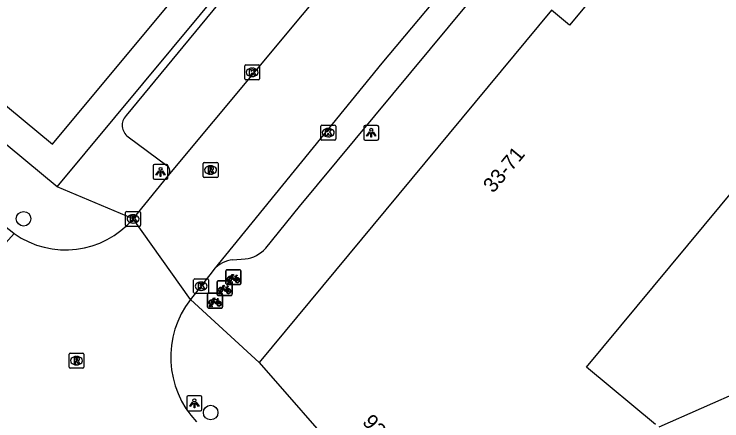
# Model space of a CAD drawing. Extents: x 162074 to 163034, y 381824 to 382557.
# Drawn here: x 162266.75 to 162314.17, y 382043.06 to 382070.34 of the extents above; entities that cross this region are included whole.
import ezdxf

# ---------------------------------------------------------------- set-up
doc = ezdxf.new("R2010")
doc.units = 0
for name, color, linetype in [('IMGEO_Boom', 7, 'Continuous'), ('IMGEO_Fietsenrek', 7, 'Continuous'), ('IMGEO_Kolk', 7, 'Continuous'), ('IMGEO_Lichtpunt', 7, 'Continuous'), ('IMGEO_Pand', 7, 'Continuous'), ('IMGEO_Pand_nummerreeks', 7, 'Continuous'), ('IMGEO_Rijbaan_lokaal_open', 7, 'Continuous'), ('IMGEO_Rioolput', 7, 'Continuous'), ('IMGEO_Voetpad_open', 7, 'Continuous')]:
    doc.layers.add(name, color=color, linetype=linetype)

msp = doc.modelspace()

# ---------------------------------------------------------------- linework, layer by layer
at = {"layer": 'IMGEO_Boom'}
for centre in [(162267.372, 382056.618), (162279.913, 382043.619)]:
    msp.add_circle(centre, 0.489, dxfattribs=at)
at = {"layer": 'IMGEO_Fietsenrek'}
for p, q in [((162280.94, 382052.275), (162280.94, 382053.116)), ((162280.94, 382053.116), (162280.94, 382052.275)), ((162281.015, 382053.2), (162281.856, 382053.2)), ((162281.856, 382053.2), (162281.015, 382053.2)), ((162281.94, 382053.125), (162281.94, 382052.284)), ((162281.94, 382052.284), (162281.94, 382053.125)), ((162281.627, 382052.749), (162281.663, 382052.654)), ((162280.344, 382051.54), (162280.344, 382052.381)), ((162280.344, 382052.381), (162280.344, 382051.54)), ((162280.419, 382052.465), (162281.26, 382052.465)), ((162281.26, 382052.465), (162280.419, 382052.465)), ((162281.865, 382052.2), (162281.024, 382052.2)), ((162281.024, 382052.2), (162281.865, 382052.2)), ((162281.067, 382052.284), (162281.106, 382052.444)), ((162281.101, 382052.284), (162281.067, 382052.284)), ((162281.136, 382052.432), (162281.101, 382052.284)), ((162281.178, 382052.456), (162281.177, 382052.46)), ((162281.219, 382052.284), (162281.185, 382052.426)), ((162281.209, 382052.467), (162281.21, 382052.46)), ((162281.217, 382052.43), (162281.252, 382052.284)), ((162281.252, 382052.284), (162281.219, 382052.284)), ((162281.344, 382052.39), (162281.344, 382051.549)), ((162281.344, 382051.549), (162281.344, 382052.39)), ((162279.783, 382051.622), (162280.624, 382051.622)), ((162280.624, 382051.622), (162279.783, 382051.622)), ((162280.471, 382051.549), (162280.51, 382051.709)), ((162280.54, 382051.697), (162280.505, 382051.549)), ((162280.582, 382051.721), (162280.581, 382051.725)), ((162280.623, 382051.549), (162280.589, 382051.691)), ((162280.613, 382051.732), (162280.614, 382051.725)), ((162280.621, 382051.695), (162280.656, 382051.549)), ((162281.031, 382052.014), (162281.067, 382051.919)), ((162279.708, 382050.697), (162279.708, 382051.538)), ((162279.708, 382051.538), (162279.708, 382050.697)), ((162280.395, 382051.171), (162280.431, 382051.076)), ((162281.269, 382051.465), (162280.428, 382051.465)), ((162280.428, 382051.465), (162281.269, 382051.465)), ((162280.505, 382051.549), (162280.471, 382051.549)), ((162280.656, 382051.549), (162280.623, 382051.549)), ((162280.708, 382051.547), (162280.708, 382050.706)), ((162280.708, 382050.706), (162280.708, 382051.547)), ((162280.633, 382050.622), (162279.792, 382050.622)), ((162279.792, 382050.622), (162280.633, 382050.622)), ((162279.835, 382050.706), (162279.874, 382050.866)), ((162279.869, 382050.706), (162279.835, 382050.706)), ((162279.904, 382050.854), (162279.869, 382050.706)), ((162279.946, 382050.878), (162279.945, 382050.882)), ((162279.987, 382050.706), (162279.953, 382050.848)), ((162279.977, 382050.889), (162279.978, 382050.882)), ((162279.985, 382050.852), (162280.02, 382050.706)), ((162280.02, 382050.706), (162279.987, 382050.706))]:
    msp.add_line(p, q, dxfattribs=at)
for points in [[(162281.274, 382052.674), (162281.222, 382052.584), (162281.182, 382052.559), (162281.183, 382052.606), (162281.238, 382052.7)], [(162281.253, 382052.726), (162281.348, 382052.89), (162281.434, 382052.876), (162281.436, 382052.867), (162281.38, 382052.856), (162281.353, 382052.811), (162281.609, 382052.77)], [(162281.549, 382052.482), (162281.499, 382052.482), (162281.308, 382052.733), (162281.289, 382052.701)], [(162281.596, 382052.745), (162281.339, 382052.786), (162281.322, 382052.757), (162281.489, 382052.537), (162281.596, 382052.745)], [(162281.644, 382052.647), (162281.614, 382052.724), (162281.505, 382052.506), (162281.548, 382052.506)], [(162281.578, 382052.506), (162281.698, 382052.505), (162281.654, 382052.619)], [(162281.674, 382052.626), (162281.729, 382052.481), (162281.579, 382052.481)], [(162281.609, 382052.77), (162281.634, 382052.819), (162281.628, 382052.823), (162281.605, 382052.827), (162281.593, 382052.834), (162281.592, 382052.837), (162281.594, 382052.842), (162281.689, 382052.827), (162281.691, 382052.817), (162281.681, 382052.804), (162281.669, 382052.798), (162281.655, 382052.804), (162281.627, 382052.749)], [(162280.657, 382051.991), (162280.752, 382052.155), (162280.838, 382052.141), (162280.84, 382052.132), (162280.784, 382052.121), (162280.757, 382052.076), (162281.013, 382052.035)], [(162281, 382052.01), (162280.743, 382052.051), (162280.726, 382052.022), (162280.893, 382051.802), (162281, 382052.01)], [(162281.013, 382052.035), (162281.038, 382052.084), (162281.032, 382052.088), (162281.009, 382052.092), (162280.997, 382052.099), (162280.996, 382052.102), (162280.998, 382052.107), (162281.093, 382052.092), (162281.095, 382052.082), (162281.085, 382052.069), (162281.073, 382052.063), (162281.059, 382052.069), (162281.031, 382052.014)], [(162280.678, 382051.939), (162280.626, 382051.849), (162280.586, 382051.824), (162280.587, 382051.871), (162280.642, 382051.965)], [(162280.953, 382051.747), (162280.903, 382051.747), (162280.712, 382051.998), (162280.693, 382051.966)], [(162281.048, 382051.912), (162281.018, 382051.989), (162280.909, 382051.771), (162280.952, 382051.771)], [(162280.982, 382051.771), (162281.102, 382051.77), (162281.058, 382051.884)], [(162281.078, 382051.891), (162281.133, 382051.746), (162280.983, 382051.746)], [(162280.042, 382051.096), (162279.99, 382051.006), (162279.95, 382050.981), (162279.951, 382051.028), (162280.006, 382051.122)], [(162280.021, 382051.148), (162280.116, 382051.312), (162280.202, 382051.298), (162280.204, 382051.289), (162280.148, 382051.278), (162280.121, 382051.233), (162280.377, 382051.192)], [(162280.317, 382050.904), (162280.267, 382050.904), (162280.076, 382051.155), (162280.057, 382051.123)], [(162280.364, 382051.167), (162280.107, 382051.208), (162280.09, 382051.179), (162280.257, 382050.959), (162280.364, 382051.167)], [(162280.412, 382051.069), (162280.382, 382051.146), (162280.273, 382050.928), (162280.316, 382050.928)], [(162280.377, 382051.192), (162280.402, 382051.241), (162280.396, 382051.245), (162280.373, 382051.249), (162280.361, 382051.256), (162280.36, 382051.259), (162280.362, 382051.264), (162280.457, 382051.249), (162280.459, 382051.239), (162280.449, 382051.226), (162280.437, 382051.22), (162280.423, 382051.226), (162280.395, 382051.171)], [(162280.346, 382050.928), (162280.466, 382050.927), (162280.422, 382051.041)], [(162280.442, 382051.048), (162280.497, 382050.903), (162280.347, 382050.903)]]:
    msp.add_lwpolyline(points, dxfattribs=at)
for centre, radius, start, end in [((162281.018, 382053.122), 0.0779, 92.4484, 184.2845), ((162281.018, 382053.122), 0.0779, 92.4484, 184.2845), ((162281.862, 382053.122), 0.0779, 2.4484, 94.2845), ((162281.862, 382053.122), 0.0779, 2.4484, 94.2845), ((162281.18, 382052.585), 0.159, 62.6766, 242.1369), ((162281.18, 382052.585), 0.129, 63.3192, 238.903), ((162281.18, 382052.585), 0.129, 283.6043, 43.4302), ((162281.18, 382052.585), 0.159, 283.5766, 46.6042), ((162281.707, 382052.501), 0.159, 113.3408, 178.3217), ((162281.707, 382052.501), 0.159, 187.0065, 105.7708), ((162281.707, 382052.501), 0.129, 113.923, 177.9556), ((162281.707, 382052.501), 0.129, 188.6715, 104.5883), ((162280.422, 382052.387), 0.0779, 92.4484, 184.2845), ((162280.422, 382052.387), 0.0779, 92.4484, 184.2845), ((162281.018, 382052.278), 0.0779, 182.4484, 274.2845), ((162281.018, 382052.278), 0.0779, 182.4484, 274.2845), ((162281.16, 382052.456), 0.0499, 12.8025, 158.6934), ((162281.18, 382052.585), 0.159, 253.9967, 271.7867), ((162281.16, 382052.456), 0.0174, 12.8025, 163.4502), ((162281.18, 382052.585), 0.129, 253.415, 269.0204), ((162281.266, 382052.387), 0.0779, 2.4484, 94.2845), ((162281.266, 382052.387), 0.0779, 2.4484, 94.2845), ((162281.862, 382052.278), 0.0779, 272.4484, 4.2845), ((162281.862, 382052.278), 0.0779, 272.4484, 4.2845), ((162279.786, 382051.544), 0.0779, 92.4484, 184.2845), ((162279.786, 382051.544), 0.0779, 92.4484, 184.2845), ((162280.584, 382051.85), 0.159, 62.6766, 242.1369), ((162280.584, 382051.85), 0.129, 63.3192, 238.903), ((162280.564, 382051.721), 0.0499, 12.8025, 158.6934), ((162280.584, 382051.85), 0.159, 253.9967, 271.7867), ((162280.564, 382051.721), 0.0174, 12.8025, 163.4502), ((162280.584, 382051.85), 0.129, 253.415, 269.0204), ((162280.584, 382051.85), 0.129, 283.6043, 43.4302), ((162280.584, 382051.85), 0.159, 283.5766, 46.6042), ((162280.63, 382051.544), 0.0779, 2.4484, 94.2845), ((162280.63, 382051.544), 0.0779, 2.4484, 94.2845), ((162281.111, 382051.766), 0.159, 113.3408, 178.3217), ((162281.111, 382051.766), 0.159, 187.0065, 105.7708), ((162281.111, 382051.766), 0.129, 113.923, 177.9556), ((162281.111, 382051.766), 0.129, 188.6715, 104.5883), ((162279.948, 382051.007), 0.159, 62.6766, 242.1369), ((162279.948, 382051.007), 0.129, 63.3192, 238.903), ((162279.948, 382051.007), 0.129, 283.6043, 43.4302), ((162279.948, 382051.007), 0.159, 283.5766, 46.6042), ((162280.422, 382051.543), 0.0779, 182.4484, 274.2845), ((162280.422, 382051.543), 0.0779, 182.4484, 274.2845), ((162281.266, 382051.543), 0.0779, 272.4484, 4.2845), ((162281.266, 382051.543), 0.0779, 272.4484, 4.2845), ((162279.786, 382050.7), 0.0779, 182.4484, 274.2845), ((162279.786, 382050.7), 0.0779, 182.4484, 274.2845), ((162279.928, 382050.878), 0.0499, 12.8025, 158.6934), ((162279.948, 382051.007), 0.159, 253.9967, 271.7867), ((162279.928, 382050.878), 0.0174, 12.8025, 163.4502), ((162279.948, 382051.007), 0.129, 253.415, 269.0204), ((162280.475, 382050.923), 0.159, 113.3408, 178.3217), ((162280.475, 382050.923), 0.159, 187.0065, 105.7708), ((162280.475, 382050.923), 0.129, 113.923, 177.9556), ((162280.475, 382050.923), 0.129, 188.6715, 104.5883), ((162280.63, 382050.7), 0.0779, 272.4484, 4.2845), ((162280.63, 382050.7), 0.0779, 272.4484, 4.2845)]:
    msp.add_arc(centre, radius, start, end, dxfattribs=at)
at = {"layer": 'IMGEO_Kolk'}
for p, q in [((162282.194, 382066.012), (162282.194, 382066.864)), ((162282.269, 382066.938), (162283.121, 382066.938)), ((162283.195, 382066.864), (162283.195, 382066.012)), ((162282.682, 382066.718), (162282.707, 382066.718)), ((162283.121, 382065.938), (162282.269, 382065.938)), ((162282.705, 382066.158), (162282.68, 382066.158)), ((162287.289, 382061.968), (162287.289, 382062.82)), ((162287.364, 382062.894), (162288.216, 382062.894)), ((162287.777, 382062.674), (162287.802, 382062.674)), ((162288.29, 382062.82), (162288.29, 382061.968)), ((162287.8, 382062.114), (162287.775, 382062.114)), ((162288.216, 382061.894), (162287.364, 382061.894)), ((162274.214, 382056.18), (162274.214, 382057.032)), ((162274.289, 382057.106), (162275.141, 382057.106)), ((162274.702, 382056.886), (162274.727, 382056.886)), ((162275.215, 382057.032), (162275.215, 382056.18)), ((162274.725, 382056.326), (162274.7, 382056.326)), ((162275.141, 382056.106), (162274.289, 382056.106)), ((162278.774, 382051.67), (162278.774, 382052.522)), ((162278.849, 382052.596), (162279.701, 382052.596)), ((162279.775, 382052.522), (162279.775, 382051.67)), ((162279.262, 382052.376), (162279.287, 382052.376)), ((162279.701, 382051.596), (162278.849, 382051.596)), ((162279.285, 382051.816), (162279.26, 382051.816))]:
    msp.add_line(p, q, dxfattribs=at)
for points in [[(162282.194, 382066.012), (162282.194, 382066.864)], [(162282.269, 382066.938), (162283.121, 382066.938)], [(162283.195, 382066.864), (162283.195, 382066.012)], [(162282.515, 382066.638), (162282.638, 382066.638), (162282.638, 382066.487), (162282.768, 382066.638), (162282.932, 382066.638), (162282.786, 382066.487), (162282.939, 382066.238), (162282.787, 382066.238), (162282.702, 382066.402), (162282.638, 382066.335), (162282.638, 382066.238), (162282.515, 382066.238), (162282.515, 382066.638)], [(162283.121, 382065.938), (162282.269, 382065.938)], [(162287.289, 382061.968), (162287.289, 382062.82)], [(162287.364, 382062.894), (162288.216, 382062.894)], [(162287.61, 382062.594), (162287.733, 382062.594), (162287.733, 382062.443), (162287.863, 382062.594), (162288.027, 382062.594), (162287.881, 382062.443), (162288.034, 382062.194), (162287.882, 382062.194), (162287.797, 382062.358), (162287.733, 382062.291), (162287.733, 382062.194), (162287.61, 382062.194), (162287.61, 382062.594)], [(162288.29, 382062.82), (162288.29, 382061.968)], [(162288.216, 382061.894), (162287.364, 382061.894)], [(162274.214, 382056.18), (162274.214, 382057.032)], [(162274.289, 382057.106), (162275.141, 382057.106)], [(162274.535, 382056.806), (162274.658, 382056.806), (162274.658, 382056.655), (162274.788, 382056.806), (162274.952, 382056.806), (162274.806, 382056.655), (162274.959, 382056.406), (162274.807, 382056.406), (162274.722, 382056.57), (162274.658, 382056.503), (162274.658, 382056.406), (162274.535, 382056.406), (162274.535, 382056.806)], [(162275.215, 382057.032), (162275.215, 382056.18)], [(162275.141, 382056.106), (162274.289, 382056.106)], [(162278.774, 382051.67), (162278.774, 382052.522)], [(162278.849, 382052.596), (162279.701, 382052.596)], [(162279.775, 382052.522), (162279.775, 382051.67)], [(162279.095, 382052.296), (162279.218, 382052.296), (162279.218, 382052.145), (162279.348, 382052.296), (162279.512, 382052.296), (162279.366, 382052.145), (162279.519, 382051.896), (162279.367, 382051.896), (162279.282, 382052.06), (162279.218, 382051.993), (162279.218, 382051.896), (162279.095, 382051.896), (162279.095, 382052.296)], [(162279.701, 382051.596), (162278.849, 382051.596)]]:
    msp.add_lwpolyline(points, dxfattribs=at)
for centre, start, end in [((162282.271, 382066.862), 91.552, 178.448), ((162282.271, 382066.862), 91.552, 178.448), ((162283.119, 382066.862), 1.552, 88.448), ((162283.119, 382066.862), 1.552, 88.448), ((162282.271, 382066.014), 181.552, 268.448), ((162282.271, 382066.014), 181.552, 268.448), ((162283.119, 382066.014), 271.552, 358.448), ((162283.119, 382066.014), 271.552, 358.448), ((162287.366, 382062.818), 91.552, 178.448), ((162287.366, 382062.818), 91.552, 178.448), ((162288.214, 382062.818), 1.552, 88.448), ((162288.214, 382062.818), 1.552, 88.448), ((162287.366, 382061.97), 181.552, 268.448), ((162287.366, 382061.97), 181.552, 268.448), ((162288.214, 382061.97), 271.552, 358.448), ((162288.214, 382061.97), 271.552, 358.448), ((162274.291, 382057.03), 91.552, 178.448), ((162274.291, 382057.03), 91.552, 178.448), ((162275.139, 382057.03), 1.552, 88.448), ((162275.139, 382057.03), 1.552, 88.448), ((162274.291, 382056.182), 181.552, 268.448), ((162274.291, 382056.182), 181.552, 268.448), ((162275.139, 382056.182), 271.552, 358.448), ((162275.139, 382056.182), 271.552, 358.448), ((162278.851, 382052.52), 91.552, 178.448), ((162278.851, 382052.52), 91.552, 178.448), ((162279.699, 382052.52), 1.552, 88.448), ((162279.699, 382052.52), 1.552, 88.448), ((162278.851, 382051.672), 181.552, 268.448), ((162278.851, 382051.672), 181.552, 268.448), ((162279.699, 382051.672), 271.552, 358.448), ((162279.699, 382051.672), 271.552, 358.448)]:
    msp.add_arc(centre, 0.0765, start, end, dxfattribs=at)
for centre, major_axis, ratio, start_param, end_param in [((162282.681, 382066.438), (-0.387, 0.002), 0.722429, 4.712389, 7.853982), ((162282.706, 382066.438), (-0.39, 0.002), 0.717154, 1.570796, 4.712389), ((162287.776, 382062.394), (-0.387, 0.002), 0.722429, 4.712389, 7.853982), ((162287.801, 382062.394), (-0.39, 0.002), 0.717154, 1.570796, 4.712389), ((162274.701, 382056.606), (-0.387, 0.002), 0.722429, 4.712389, 7.853982), ((162274.726, 382056.606), (-0.39, 0.002), 0.717154, 1.570796, 4.712389), ((162279.261, 382052.096), (-0.387, 0.002), 0.722429, 4.712389, 7.853982), ((162279.286, 382052.096), (-0.39, 0.002), 0.717154, 1.570796, 4.712389)]:
    msp.add_ellipse(centre, major_axis=major_axis, ratio=ratio, start_param=start_param, end_param=end_param, dxfattribs=at)
at = {"layer": 'IMGEO_Lichtpunt'}
for p, q in [((162290.177, 382062.788), (162290.177, 382061.981)), ((162290.177, 382062.788), (162290.177, 382061.981)), ((162291.079, 382062.883), (162290.271, 382062.883)), ((162291.079, 382062.883), (162290.271, 382062.883)), ((162291.173, 382061.981), (162291.173, 382062.788)), ((162291.173, 382061.981), (162291.173, 382062.788)), ((162290.271, 382061.887), (162291.079, 382061.887)), ((162290.271, 382061.887), (162291.079, 382061.887)), ((162276.056, 382060.164), (162276.056, 382059.357)), ((162276.056, 382060.164), (162276.056, 382059.357)), ((162276.958, 382060.259), (162276.15, 382060.259)), ((162276.958, 382060.259), (162276.15, 382060.259)), ((162277.052, 382059.357), (162277.052, 382060.164)), ((162277.052, 382059.357), (162277.052, 382060.164)), ((162276.15, 382059.263), (162276.958, 382059.263)), ((162276.15, 382059.263), (162276.958, 382059.263)), ((162278.321, 382044.642), (162278.321, 382043.835)), ((162278.321, 382044.642), (162278.321, 382043.835)), ((162279.223, 382044.737), (162278.415, 382044.737)), ((162279.223, 382044.737), (162278.415, 382044.737)), ((162279.317, 382043.835), (162279.317, 382044.642)), ((162279.317, 382043.835), (162279.317, 382044.642)), ((162278.415, 382043.741), (162279.223, 382043.741)), ((162278.415, 382043.741), (162279.223, 382043.741))]:
    msp.add_line(p, q, dxfattribs=at)
for points in [[(162290.551, 382062.452), (162290.59, 382062.424), (162290.402, 382062.162), (162290.364, 382062.189), (162290.551, 382062.452)], [(162290.653, 382062.404), (162290.7, 382062.404), (162290.7, 382062.082), (162290.653, 382062.082), (162290.653, 382062.404)], [(162290.763, 382062.424), (162290.801, 382062.451), (162290.988, 382062.189), (162290.949, 382062.161), (162290.763, 382062.424)], [(162276.43, 382059.828), (162276.469, 382059.8), (162276.281, 382059.538), (162276.243, 382059.565), (162276.43, 382059.828)], [(162276.532, 382059.78), (162276.579, 382059.78), (162276.579, 382059.458), (162276.532, 382059.458), (162276.532, 382059.78)], [(162276.642, 382059.8), (162276.68, 382059.827), (162276.867, 382059.565), (162276.828, 382059.537), (162276.642, 382059.8)], [(162278.695, 382044.306), (162278.734, 382044.278), (162278.546, 382044.016), (162278.508, 382044.043), (162278.695, 382044.306)], [(162278.797, 382044.258), (162278.844, 382044.258), (162278.844, 382043.936), (162278.797, 382043.936), (162278.797, 382044.258)], [(162278.907, 382044.278), (162278.945, 382044.305), (162279.132, 382044.043), (162279.093, 382044.015), (162278.907, 382044.278)]]:
    msp.add_lwpolyline(points, dxfattribs=at)
for centre in [(162290.676, 382062.586), (162276.555, 382059.962), (162278.82, 382044.44)]:
    msp.add_circle(centre, 0.0994, dxfattribs=at)
for centre, start, end in [((162290.271, 382062.788), 90, 180), ((162290.271, 382062.788), 90, 180), ((162291.079, 382062.788), 0, 90), ((162291.079, 382062.788), 0, 90), ((162290.271, 382061.981), 180, 270), ((162290.271, 382061.981), 180, 270), ((162291.079, 382061.981), 270, 0), ((162291.079, 382061.981), 270, 360), ((162276.15, 382060.164), 90, 180), ((162276.15, 382060.164), 90, 180), ((162276.958, 382060.164), 0, 90), ((162276.958, 382060.164), 0, 90), ((162276.15, 382059.357), 180, 270), ((162276.15, 382059.357), 180, 270), ((162276.958, 382059.357), 270, 0), ((162276.958, 382059.357), 270, 360), ((162278.415, 382044.642), 90, 180), ((162278.415, 382044.642), 90, 180), ((162279.223, 382044.642), 0, 90), ((162279.223, 382044.642), 0, 90), ((162278.415, 382043.835), 180, 270), ((162278.415, 382043.835), 180, 270), ((162279.223, 382043.835), 270, 0), ((162279.223, 382043.835), 270, 360)]:
    msp.add_arc(centre, 0.0946, start, end, dxfattribs=at)
at = {"layer": 'IMGEO_Pand'}
for points in [[(162257.354, 382071.559), (162269.325, 382061.62), (162287.263, 382083.228)], [(162311.856, 382079.111), (162303.966, 382069.599), (162302.753, 382070.605), (162283.157, 382046.98)], [(162309.723, 382042.825), (162305.101, 382046.658), (162320.873, 382065.674), (162324.065, 382069.522)], [(162283.157, 382046.98), (162294.651, 382033.839)], [(162318.916, 382041.378), (162315.622, 382045.145), (162309.954, 382042.634)]]:
    msp.add_lwpolyline(points, dxfattribs=at)
at = {"layer": 'IMGEO_Rijbaan_lokaal_open'}
for points in [[(162266.745, 382055.63), (162265.389, 382054.128), (162243.321, 382074.12), (162210.014, 382101.13)], [(162302.72, 382080.595), (162291.389, 382067.054), (162280.133, 382053.209)], [(162277.076, 382059.503), (162292.02, 382077.479)], [(162274.715, 382056.606), (162277.076, 382059.503)], [(162278.563, 382051.21), (162274.715, 382056.606)], [(162280.133, 382053.209), (162280.019, 382053.069), (162278.563, 382051.21)]]:
    msp.add_lwpolyline(points, dxfattribs=at)
for centre, radius, start, end in [((162270.195, 382060.485), 5.956, 234.5992, 319.364), ((162283.576, 382047.335), 6.336, 142.2932, 223.2264)]:
    msp.add_arc(centre, radius, start, end, dxfattribs=at)
at = {"layer": 'IMGEO_Rioolput'}
for p, q in [((162279.404, 382059.462), (162279.404, 382060.314)), ((162279.479, 382060.388), (162280.331, 382060.388)), ((162279.892, 382060.168), (162279.917, 382060.168)), ((162280.405, 382060.314), (162280.405, 382059.462)), ((162280.331, 382059.388), (162279.479, 382059.388)), ((162279.915, 382059.608), (162279.89, 382059.608)), ((162270.423, 382046.674), (162270.423, 382047.526)), ((162270.498, 382047.6), (162271.35, 382047.6)), ((162270.911, 382047.38), (162270.936, 382047.38)), ((162271.424, 382047.526), (162271.424, 382046.674)), ((162271.35, 382046.6), (162270.498, 382046.6)), ((162270.934, 382046.82), (162270.909, 382046.82))]:
    msp.add_line(p, q, dxfattribs=at)
for points in [[(162279.404, 382059.462), (162279.404, 382060.314)], [(162279.479, 382060.388), (162280.331, 382060.388)], [(162280.405, 382060.314), (162280.405, 382059.462)], [(162279.993, 382060.086), (162279.741, 382060.088), (162279.741, 382059.688)], [(162279.741, 382059.688), (162279.865, 382059.688), (162279.865, 382059.85), (162279.876, 382059.85)], [(162279.919, 382060.007), (162279.865, 382060.007), (162279.865, 382059.926)], [(162279.865, 382059.926), (162279.917, 382059.926)], [(162279.923, 382059.821), (162279.994, 382059.688), (162280.134, 382059.688), (162280.069, 382059.814)], [(162280.331, 382059.388), (162279.479, 382059.388)], [(162270.423, 382046.674), (162270.423, 382047.526)], [(162270.498, 382047.6), (162271.35, 382047.6)], [(162271.424, 382047.526), (162271.424, 382046.674)], [(162271.012, 382047.298), (162270.76, 382047.3), (162270.76, 382046.9)], [(162270.76, 382046.9), (162270.884, 382046.9), (162270.884, 382047.062), (162270.895, 382047.062)], [(162270.938, 382047.219), (162270.884, 382047.219), (162270.884, 382047.138)], [(162270.884, 382047.138), (162270.936, 382047.138)], [(162270.942, 382047.033), (162271.013, 382046.9), (162271.153, 382046.9), (162271.088, 382047.026)], [(162271.35, 382046.6), (162270.498, 382046.6)]]:
    msp.add_lwpolyline(points, dxfattribs=at)
for centre, radius, start, end in [((162279.481, 382060.312), 0.0765, 91.552, 178.448), ((162279.481, 382060.312), 0.0765, 91.552, 178.448), ((162280.329, 382060.312), 0.0765, 1.552, 88.448), ((162280.329, 382060.312), 0.0765, 1.552, 88.448), ((162279.875, 382059.797), 0.0533, 26.0293, 88.6989), ((162279.901, 382060.115), 0.19, 274.7715, 282.9687), ((162279.925, 382059.911), 0.0964, 77.0061, 93.1865), ((162279.939, 382059.968), 0.0378, 276.6634, 79.6772), ((162279.992, 382059.976), 0.109, 350.3612, 89.416), ((162279.99, 382059.976), 0.112, 277.5842, 350.9817), ((162279.974, 382059.761), 0.108, 29.5134, 73.7905), ((162279.481, 382059.464), 0.0765, 181.552, 268.448), ((162279.481, 382059.464), 0.0765, 181.552, 268.448), ((162280.329, 382059.464), 0.0765, 271.552, 358.448), ((162280.329, 382059.464), 0.0765, 271.552, 358.448), ((162270.5, 382047.524), 0.0765, 91.552, 178.448), ((162270.5, 382047.524), 0.0765, 91.552, 178.448), ((162271.348, 382047.524), 0.0765, 1.552, 88.448), ((162271.348, 382047.524), 0.0765, 1.552, 88.448), ((162270.894, 382047.009), 0.0533, 26.0293, 88.6989), ((162270.92, 382047.327), 0.19, 274.7715, 282.9687), ((162270.944, 382047.123), 0.0964, 77.0061, 93.1865), ((162270.958, 382047.18), 0.0378, 276.6634, 79.6772), ((162271.011, 382047.188), 0.109, 350.3612, 89.416), ((162271.009, 382047.188), 0.112, 277.5842, 350.9817), ((162270.993, 382046.973), 0.108, 29.5134, 73.7905), ((162270.5, 382046.676), 0.0765, 181.552, 268.448), ((162270.5, 382046.676), 0.0765, 181.552, 268.448), ((162271.348, 382046.676), 0.0765, 271.552, 358.448), ((162271.348, 382046.676), 0.0765, 271.552, 358.448)]:
    msp.add_arc(centre, radius, start, end, dxfattribs=at)
for centre, major_axis, ratio, start_param, end_param in [((162279.891, 382059.888), (-0.387, 0.002), 0.722429, 4.712389, 7.853982), ((162279.916, 382059.888), (-0.39, 0.002), 0.717154, 1.570796, 4.712389), ((162270.91, 382047.1), (-0.387, 0.002), 0.722429, 4.712389, 7.853982), ((162270.935, 382047.1), (-0.39, 0.002), 0.717154, 1.570796, 4.712389)]:
    msp.add_ellipse(centre, major_axis=major_axis, ratio=ratio, start_param=start_param, end_param=end_param, dxfattribs=at)
at = {"layer": 'IMGEO_Voetpad_open'}
for points in [[(162269.629, 382058.768), (162288.836, 382081.903)], [(162287.336, 382079.444), (162274.242, 382063.537)], [(162283.602, 382054.641), (162285.856, 382057.451), (162302.108, 382077.033)], [(162269.629, 382058.768), (162252.136, 382073.29), (162252.731, 382074.006)], [(162274.377, 382062.117), (162276.986, 382060.2)], [(162274.715, 382056.606), (162269.629, 382058.768)], [(162266.007, 382056.221), (162266.608, 382055.73), (162266.745, 382055.63)], [(162281.392, 382053.871), (162282.223, 382053.927)], [(162278.563, 382051.21), (162283.157, 382046.98)]]:
    msp.add_lwpolyline(points, dxfattribs=at)
for centre, radius, start, end in [((162274.942, 382062.887), 0.955, 137.1131, 233.7485), ((162276.698, 382059.809), 0.486, 321.0504, 53.6647), ((162281.985, 382056.076), 2.162, 276.3253, 318.422), ((162281.645, 382051.863), 2.024, 97.166, 138.3061)]:
    msp.add_arc(centre, radius, start, end, dxfattribs=at)

# ---------------------------------------------------------------- texts
at = {"layer": 'IMGEO_Pand_nummerreeks'}
for s, rotation, p in [('33-71', 50.325, (162298.848, 382058.291)), ('93', 311.1751, (162290.027, 382042.954))]:
    msp.add_text(s, height=1, rotation=rotation, dxfattribs=at).set_placement(p)

doc.saveas('drawing.dxf')
